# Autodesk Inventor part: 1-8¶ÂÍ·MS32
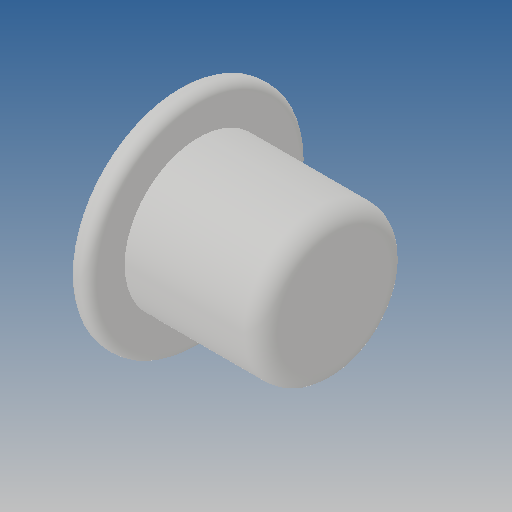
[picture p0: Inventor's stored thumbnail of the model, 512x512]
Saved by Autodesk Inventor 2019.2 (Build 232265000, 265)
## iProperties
Created: 2013-07
Part Number: 1-8¶ÂÍ·MS32
Material: Ogólny
Document SubType Name: Modeling
Designer: CADENGINEERING4
Density: 1 g/cm^3
Appearance: Domyślna
Author: CADENGINEERING4
Revision Number: ÈÎºÎ
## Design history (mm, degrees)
feature "Ô²½Ç2"
node "Bryła1"
